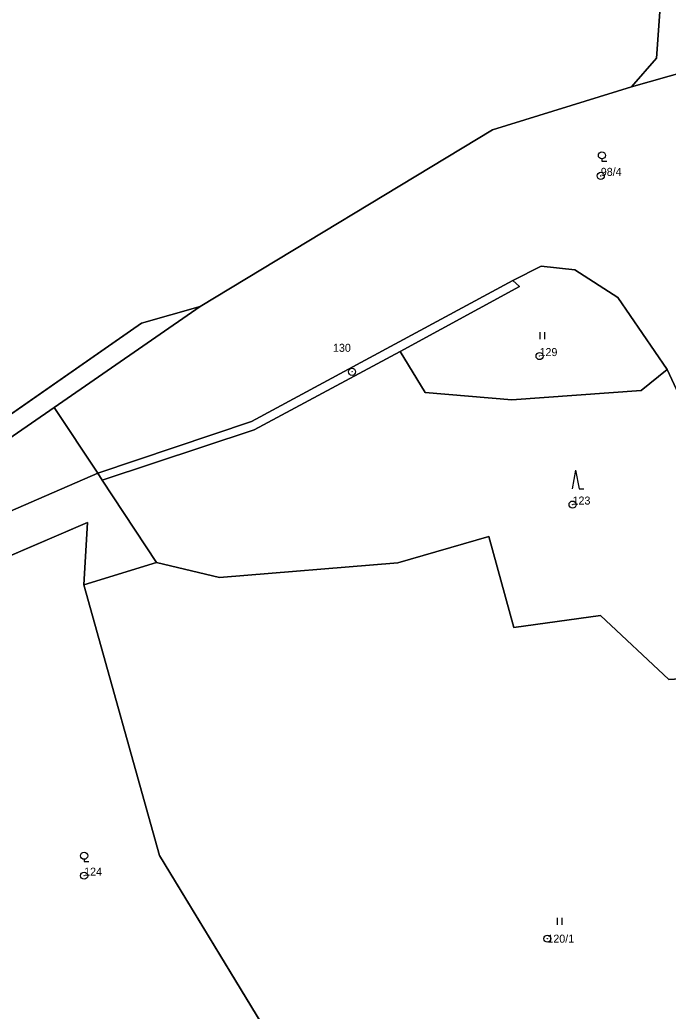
# Model space of a CAD drawing. Extents: x -652854 to -650068, y -1097661 to -1095417.
# Drawn here: x -650641.1 to -650503.2, y -1096048.9 to -1095838.2 of the extents above; entities that cross this region are included whole.
import ezdxf

# ---------------------------------------------------------------- set-up
doc = ezdxf.new("R2010")
doc.units = 0
for name, color, linetype in [('Definiční body parcel', 7, 'Continuous'), ('Hranice parcel', 7, 'Continuous'), ('Obvody jako plochy', 7, 'Continuous'), ('Parcelní čísla', 7, 'Continuous'), ('Prvky pro prodl_ par_ č_', 7, 'Continuous'), ('Značky kultur', 7, 'Continuous')]:
    doc.layers.add(name, color=color, linetype=linetype)

msp = doc.modelspace()

# ---------------------------------------------------------------- linework, layer by layer
at = {"layer": 'Definiční body parcel'}
for centre, radius in [((-650517.58, -1095871.36), 0.75), ((-650517.58, -1095871.36), 0.0327), ((-650530.6, -1095909.66), 0.75), ((-650530.6, -1095909.66), 0.0327), ((-650570.47, -1095913), 0.75), ((-650570.47, -1095913), 0.0327), ((-650523.58, -1095941.21), 0.75), ((-650523.58, -1095941.21), 0.0327), ((-650627.42, -1096020.07), 0.75), ((-650627.42, -1096020.07), 0.0327), ((-650528.93, -1096033.46), 0.75), ((-650528.93, -1096033.46), 0.0327)]:
    msp.add_circle(centre, radius, dxfattribs=at)
at = {"layer": 'Hranice parcel'}
for p, q in [((-650505.7, -1095846.33), (-650504.91, -1095834.49)), ((-650511.07, -1095852.45), (-650505.7, -1095846.33)), ((-650499.26, -1095849.08), (-650511.07, -1095852.45)), ((-650511.07, -1095852.45), (-650540.62, -1095861.56)), ((-650540.62, -1095861.56), (-650602.74, -1095899.15)), ((-650536.25, -1095893.58), (-650530.27, -1095890.56)), ((-650530.27, -1095890.56), (-650523.09, -1095891.3)), ((-650523.09, -1095891.3), (-650513.93, -1095897.24)), ((-650591.87, -1095923.58), (-650536.25, -1095893.58)), ((-650534.86, -1095894.9), (-650536.25, -1095893.58)), ((-650560.23, -1095908.72), (-650534.86, -1095894.9)), ((-650513.93, -1095897.24), (-650503.45, -1095912.48)), ((-650602.74, -1095899.15), (-650633.81, -1095920.58)), ((-650602.74, -1095899.15), (-650615.21, -1095902.66)), ((-650615.21, -1095902.66), (-650663.79, -1095936.46)), ((-650560.23, -1095908.72), (-650591.29, -1095925.33)), ((-650554.95, -1095917.41), (-650560.23, -1095908.72)), ((-650503.45, -1095912.48), (-650508.96, -1095916.95)), ((-650496.43, -1095927.53), (-650503.45, -1095912.48)), ((-650508.96, -1095916.95), (-650536.51, -1095918.98)), ((-650536.51, -1095918.98), (-650554.95, -1095917.41)), ((-650633.81, -1095920.58), (-650658.15, -1095937.4)), ((-650633.81, -1095920.58), (-650624.51, -1095934.57)), ((-650624.51, -1095934.57), (-650591.87, -1095923.58)), ((-650591.29, -1095925.33), (-650623.58, -1095936.04)), ((-650624.51, -1095934.57), (-650665.5, -1095952.31)), ((-650623.58, -1095936.04), (-650624.51, -1095934.57)), ((-650623.58, -1095936.04), (-650612.04, -1095953.51)), ((-650626.69, -1095945), (-650650.16, -1095955.09)), ((-650627.52, -1095958.3), (-650626.69, -1095945)), ((-650541.4, -1095948.01), (-650560.74, -1095953.56)), ((-650536.05, -1095967.37), (-650541.4, -1095948.01)), ((-650612.04, -1095953.51), (-650627.52, -1095958.3)), ((-650598.64, -1095956.71), (-650612.04, -1095953.51)), ((-650560.74, -1095953.56), (-650598.64, -1095956.71)), ((-650611.4, -1096015.81), (-650627.52, -1095958.3)), ((-650517.67, -1095964.75), (-650536.05, -1095967.37)), ((-650503.12, -1095978.41), (-650517.67, -1095964.75)), ((-650580.06, -1096067.29), (-650611.4, -1096015.81))]:
    msp.add_line(p, q, dxfattribs=at)
at = {"layer": 'Obvody jako plochy'}
for points in [[(-650494.84, -1095839.58), (-650476.53, -1095813.53), (-650471.89, -1095808.33), (-650467.96, -1095793.34), (-650478.74, -1095784.29), (-650495.09, -1095809.68), (-650504.91, -1095834.49), (-650505.7, -1095846.33), (-650511.07, -1095852.45), (-650499.26, -1095849.08)], [(-650624.51, -1095934.57), (-650591.87, -1095923.58), (-650536.25, -1095893.58), (-650530.27, -1095890.56), (-650523.09, -1095891.3), (-650513.93, -1095897.24), (-650503.45, -1095912.48), (-650496.43, -1095927.53), (-650487.46, -1095903.53), (-650499.26, -1095849.08), (-650511.07, -1095852.45), (-650540.62, -1095861.56), (-650602.74, -1095899.15), (-650633.81, -1095920.58)], [(-650560.23, -1095908.72), (-650554.95, -1095917.41), (-650536.51, -1095918.98), (-650508.96, -1095916.95), (-650503.45, -1095912.48), (-650513.93, -1095897.24), (-650523.09, -1095891.3), (-650530.27, -1095890.56), (-650536.25, -1095893.58), (-650534.86, -1095894.9)], [(-650560.23, -1095908.72), (-650534.86, -1095894.9), (-650536.25, -1095893.58), (-650591.87, -1095923.58), (-650624.51, -1095934.57), (-650623.58, -1095936.04), (-650591.29, -1095925.33)], [(-650602.74, -1095899.15), (-650615.21, -1095902.66), (-650663.79, -1095936.46), (-650678.58, -1095942.65), (-650699.94, -1095950.82), (-650683.81, -1095953.04), (-650658.15, -1095937.4), (-650633.81, -1095920.58)], [(-650464.19, -1095965.63), (-650478.81, -1095954.04), (-650496.43, -1095927.53), (-650503.45, -1095912.48), (-650508.96, -1095916.95), (-650536.51, -1095918.98), (-650554.95, -1095917.41), (-650560.23, -1095908.72), (-650591.29, -1095925.33), (-650623.58, -1095936.04), (-650612.04, -1095953.51), (-650598.64, -1095956.71), (-650560.74, -1095953.56), (-650541.4, -1095948.01), (-650536.05, -1095967.37), (-650517.67, -1095964.75), (-650503.12, -1095978.41), (-650493.33, -1095977.79), (-650487.55, -1095984.67), (-650476.14, -1095976.88), (-650466.48, -1095968.02)], [(-650624.51, -1095934.57), (-650633.81, -1095920.58), (-650658.15, -1095937.4), (-650683.81, -1095953.04), (-650679.13, -1095955.92), (-650665.5, -1095952.31)], [(-650681.34, -1095998.35), (-650674.69, -1096001.79), (-650675.32, -1096003.13), (-650663.2, -1096025.43), (-650655.69, -1095990.58), (-650655.71, -1095966.27), (-650650.16, -1095955.09), (-650626.69, -1095945), (-650627.52, -1095958.3), (-650612.04, -1095953.51), (-650623.58, -1095936.04), (-650624.51, -1095934.57), (-650665.5, -1095952.31), (-650679.13, -1095955.92), (-650683.21, -1095964.08), (-650673.46, -1095966.76), (-650685.7, -1095992.01), (-650687.25, -1095993.74), (-650697.45, -1096004.89), (-650687.41, -1096010.3)], [(-650613.9, -1096078.29), (-650593.69, -1096090.8), (-650580.06, -1096067.29), (-650611.4, -1096015.81), (-650627.52, -1095958.3), (-650626.69, -1095945), (-650650.16, -1095955.09), (-650655.71, -1095966.27), (-650655.69, -1095990.58), (-650663.2, -1096025.43), (-650644.26, -1096049.61)], [(-650466.48, -1095968.02), (-650476.14, -1095976.88), (-650487.55, -1095984.67), (-650493.33, -1095977.79), (-650503.12, -1095978.41), (-650517.67, -1095964.75), (-650536.05, -1095967.37), (-650541.4, -1095948.01), (-650560.74, -1095953.56), (-650598.64, -1095956.71), (-650612.04, -1095953.51), (-650627.52, -1095958.3), (-650611.4, -1096015.81), (-650580.06, -1096067.29), (-650593.69, -1096090.8), (-650589.64, -1096093.25), (-650567.4, -1096100.11), (-650500.85, -1096112.74), (-650484.72, -1096066.48), (-650468.1, -1096026.43), (-650458, -1096008.78), (-650450.36, -1095987.68), (-650448.82, -1095982.83)]]:
    msp.add_lwpolyline(points, close=True, dxfattribs=at)
msp.add_lwpolyline([(-650707.4, -1095814.79), (-650739.26, -1095845.66), (-650736.48, -1095872.46), (-650734.98, -1095874.35), (-650720.3, -1095862.69), (-650688.9, -1095901.19), (-650699.31, -1095909.75), (-650694.36, -1095914.44), (-650678.58, -1095942.65), (-650663.79, -1095936.46), (-650615.21, -1095902.66), (-650602.74, -1095899.15), (-650540.62, -1095861.56), (-650511.07, -1095852.45), (-650505.7, -1095846.33), (-650504.91, -1095834.49)], dxfattribs=at)
at = {"layer": 'Značky kultur'}
for p, q in [((-650517.34, -1095867.76), (-650517.34, -1095868.26)), ((-650517.34, -1095868.26), (-650516.317, -1095868.26)), ((-650530.527, -1095904.595), (-650530.527, -1095906.095)), ((-650529.505, -1095906.095), (-650529.505, -1095904.595)), ((-650522.942, -1095933.869), (-650523.675, -1095937.869)), ((-650522.942, -1095933.869), (-650522.209, -1095937.869)), ((-650522.209, -1095937.869), (-650521.209, -1095937.869)), ((-650627.42, -1096016.59), (-650627.42, -1096017.09)), ((-650627.42, -1096017.09), (-650626.397, -1096017.09)), ((-650526.847, -1096029.025), (-650526.847, -1096030.525)), ((-650525.825, -1096030.525), (-650525.825, -1096029.025))]:
    msp.add_line(p, q, dxfattribs=at)
for centre in [(-650517.34, -1095867.01), (-650627.42, -1096015.84)]:
    msp.add_circle(centre, 0.75, dxfattribs=at)

# ---------------------------------------------------------------- texts
at = {"layer": 'Parcelní čísla'}
for s, height, p in [('98/4', 1.7, (-650517.58, -1095871.36)), ('129', 1.7, (-650530.6, -1095909.66)), ('130', 0.1, (-650570.47, -1095913)), ('123', 1.7, (-650523.58, -1095941.21)), ('124', 1.7, (-650627.42, -1096020.07)), ('120/1', 1.7, (-650528.93, -1096034.31))]:
    msp.add_text(s, height=height, dxfattribs=at).set_placement(p)
at = {"layer": 'Prvky pro prodl_ par_ č_'}
msp.add_text('130', height=1.7, dxfattribs=at).set_placement((-650574.51, -1095908.75))

doc.saveas('drawing.dxf')
